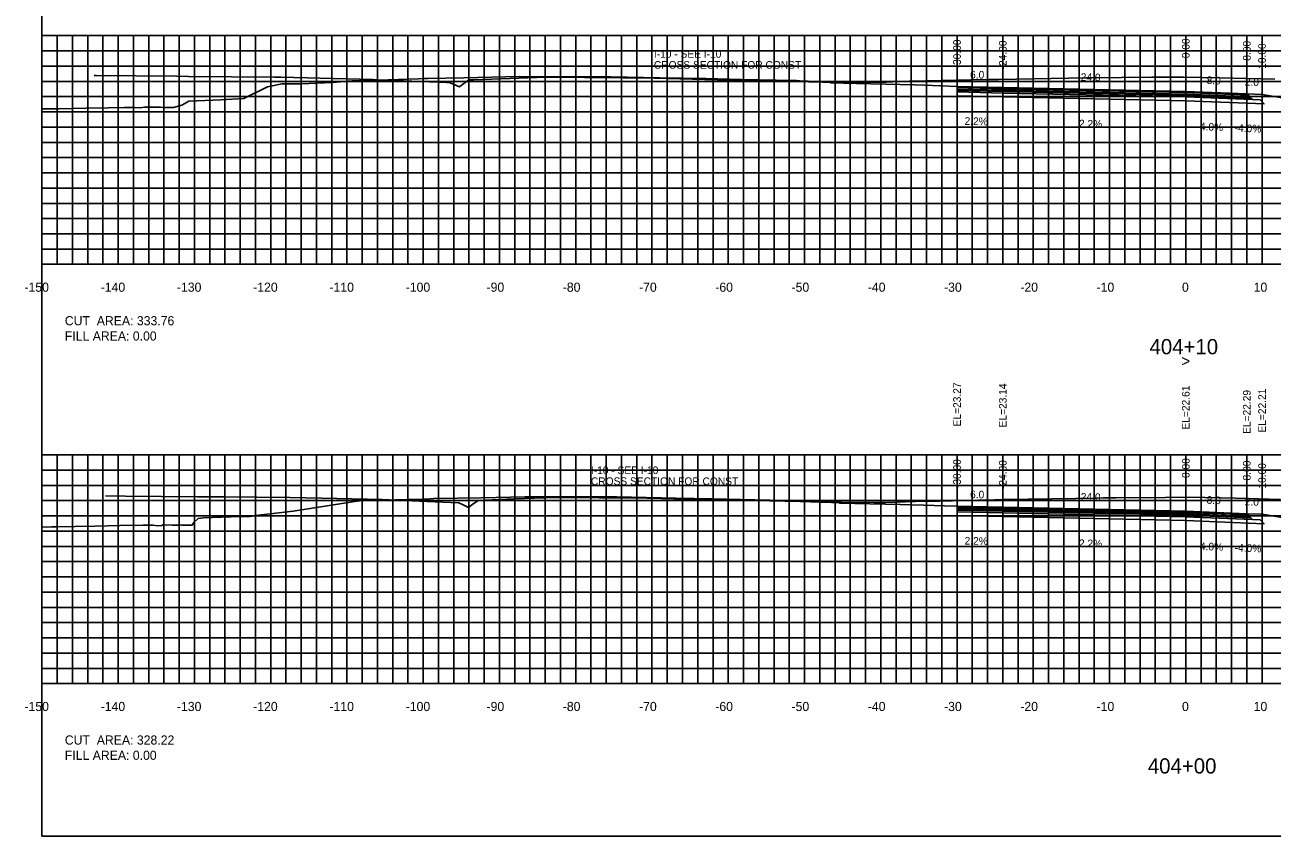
# Model space of a CAD drawing. Extents: x 1800976 to 1805104, y 250057 to 250580.
# Drawn here: x 1802478.8 to 1802642.3, y 250079.4 to 250185.8 of the extents above; entities that cross this region are included whole.
import ezdxf

# ---------------------------------------------------------------- set-up
doc = ezdxf.new("R2010")
doc.units = 0
for name, color, linetype in [('1', 7, 'Continuous'), ('10', 7, 'Continuous'), ('3', 7, 'Continuous'), ('4', 7, 'Continuous'), ('60', 7, 'Continuous'), ('ANNO-TXT', 7, 'Continuous'), ('BASE', 7, 'Continuous'), ('CL-CNST', 7, 'Continuous'), ('Level 62', 7, 'Continuous'), ('LOWER BINDER', 7, 'Continuous'), ('M-ROADS', 7, 'Continuous'), ('UPPER BINDER', 7, 'Continuous'), ('WEARING', 7, 'Continuous')]:
    doc.layers.add(name, color=color, linetype=linetype)

msp = doc.modelspace()

# ---------------------------------------------------------------- linework, layer by layer
for p, q in [((1802601, 250177.76), (1802601, 250179.76)), ((1802607, 250177.62), (1802607, 250179.62)), ((1802631, 250177.1), (1802631, 250179.1)), ((1802639, 250176.78), (1802639, 250178.78)), ((1802641, 250176.7), (1802641, 250178.7)), ((1802601, 250122.7), (1802601, 250124.7)), ((1802607, 250122.57), (1802607, 250124.57)), ((1802631, 250122.04), (1802631, 250124.04)), ((1802639, 250121.72), (1802639, 250123.72)), ((1802641, 250121.64), (1802641, 250123.64))]:
    msp.add_line(p, q)
msp.add_lwpolyline([(1802481, 250079.43), (1802781, 250079.43), (1802781, 250269.43), (1802481, 250269.43)], close=True)
at = {"layer": '60'}
for p, q in [((1802480.94, 250184.43), (1802481, 250184.43)), ((1802481, 250154.43), (1802481, 250184.43)), ((1802480.94, 250174.43), (1802481, 250174.43)), ((1802480.94, 250164.43), (1802481, 250164.43)), ((1802480.94, 250154.43), (1802481, 250154.43)), ((1802481, 250154.43), (1802781, 250154.43)), ((1802481, 250154.37), (1802481, 250154.43)), ((1802491, 250154.37), (1802491, 250154.43)), ((1802501, 250154.37), (1802501, 250154.43)), ((1802511, 250154.37), (1802511, 250154.43)), ((1802521, 250154.37), (1802521, 250154.43)), ((1802531, 250154.37), (1802531, 250154.43)), ((1802541, 250154.37), (1802541, 250154.43)), ((1802551, 250154.37), (1802551, 250154.43)), ((1802561, 250154.37), (1802561, 250154.43)), ((1802571, 250154.37), (1802571, 250154.43)), ((1802581, 250154.37), (1802581, 250154.43)), ((1802591, 250154.37), (1802591, 250154.43)), ((1802601, 250154.37), (1802601, 250154.43)), ((1802611, 250154.37), (1802611, 250154.43)), ((1802621, 250154.37), (1802621, 250154.43)), ((1802631, 250154.37), (1802631, 250154.43)), ((1802641, 250154.37), (1802641, 250154.43)), ((1802480.94, 250129.43), (1802481, 250129.43)), ((1802481, 250099.43), (1802481, 250129.43)), ((1802480.94, 250119.43), (1802481, 250119.43)), ((1802480.94, 250109.43), (1802481, 250109.43)), ((1802480.94, 250099.43), (1802481, 250099.43)), ((1802481, 250099.43), (1802781, 250099.43)), ((1802481, 250099.37), (1802481, 250099.43)), ((1802491, 250099.37), (1802491, 250099.43)), ((1802501, 250099.37), (1802501, 250099.43)), ((1802511, 250099.37), (1802511, 250099.43)), ((1802521, 250099.37), (1802521, 250099.43)), ((1802531, 250099.37), (1802531, 250099.43)), ((1802541, 250099.37), (1802541, 250099.43)), ((1802551, 250099.37), (1802551, 250099.43)), ((1802561, 250099.37), (1802561, 250099.43)), ((1802571, 250099.37), (1802571, 250099.43)), ((1802581, 250099.37), (1802581, 250099.43)), ((1802591, 250099.37), (1802591, 250099.43)), ((1802601, 250099.37), (1802601, 250099.43)), ((1802611, 250099.37), (1802611, 250099.43)), ((1802621, 250099.37), (1802621, 250099.43)), ((1802631, 250099.37), (1802631, 250099.43)), ((1802641, 250099.37), (1802641, 250099.43))]:
    msp.add_line(p, q, dxfattribs=at)
at = {"layer": 'BASE'}
for points in [[(1802601, 250177.04), (1802607, 250176.9), (1802631, 250176.38), (1802639.75, 250176.03), (1802640.75, 250175.99), (1802641.27, 250175.47), (1802631, 250175.88), (1802607, 250176.4), (1802601, 250176.54)], [(1802601, 250121.98), (1802607, 250121.85), (1802631, 250121.32), (1802639.75, 250120.97), (1802640.75, 250120.93), (1802641.27, 250120.41), (1802631, 250120.82), (1802607, 250121.35), (1802601, 250121.48)]]:
    msp.add_lwpolyline(points, close=True, dxfattribs=at)
at = {"layer": 'CL-CNST'}
for points in [[(1802487.83, 250179.19), (1802488.12, 250179.22), (1802498.64, 250179.11), (1802500.22, 250179.08), (1802511.5, 250178.97), (1802512.31, 250178.96), (1802524.36, 250178.67), (1802524.4, 250178.67), (1802524.43, 250178.67), (1802525, 250178.65), (1802534.03, 250178.28), (1802534.48, 250178.26), (1802534.54, 250178.23), (1802535.74, 250177.7), (1802535.8, 250177.74), (1802537, 250178.61), (1802537.62, 250178.64), (1802547.07, 250179), (1802557.24, 250178.89), (1802559.17, 250178.89), (1802561.33, 250178.84), (1802571.26, 250178.6), (1802574.19, 250178.53), (1802583.35, 250178.32), (1802583.64, 250178.31), (1802584.36, 250178.28), (1802584.39, 250178.24), (1802584.41, 250178.23), (1802587.83, 250178.15), (1802595.44, 250177.97), (1802596.72, 250177.92), (1802601, 250177.74)], [(1802601, 250177.76), (1802607, 250177.62), (1802631, 250177.1), (1802639, 250176.78), (1802641, 250176.7), (1802671, 250171.7), (1802675, 250171.7), (1802694.66, 250176.61)], [(1802489.32, 250124.04), (1802491.97, 250124.03), (1802501.41, 250123.94), (1802504.83, 250123.92), (1802513.51, 250123.84), (1802517.69, 250123.74), (1802525.6, 250123.56), (1802531.5, 250123.31), (1802535.67, 250123.14), (1802536.23, 250122.86), (1802536.93, 250122.55), (1802537.49, 250122.96), (1802538.19, 250123.47), (1802542.94, 250123.65), (1802548.27, 250123.85), (1802554.01, 250123.79), (1802560.36, 250123.77), (1802567.52, 250123.6), (1802572.45, 250123.48), (1802580.38, 250123.3), (1802584.55, 250123.2), (1802585.23, 250123.17), (1802585.55, 250123.16), (1802585.57, 250123.14), (1802585.61, 250123.11), (1802593.56, 250122.92), (1802596.64, 250122.85), (1802599.34, 250122.76), (1802601, 250122.69)], [(1802601, 250122.7), (1802607, 250122.57), (1802631, 250122.04), (1802639, 250121.72), (1802641, 250121.64), (1802671, 250116.64), (1802675, 250116.64), (1802694.63, 250121.55)]]:
    msp.add_lwpolyline(points, dxfattribs=at)
at = {"layer": 'Level 62'}
for p, q in [((1802481, 250184.43), (1802781, 250184.43)), ((1802481, 250154.43), (1802481, 250184.43)), ((1802483, 250154.43), (1802483, 250184.43)), ((1802485, 250154.43), (1802485, 250184.43)), ((1802487, 250154.43), (1802487, 250184.43)), ((1802489, 250154.43), (1802489, 250184.43)), ((1802491, 250154.43), (1802491, 250184.43)), ((1802493, 250154.43), (1802493, 250184.43)), ((1802495, 250154.43), (1802495, 250184.43)), ((1802497, 250154.43), (1802497, 250184.43)), ((1802499, 250154.43), (1802499, 250184.43)), ((1802501, 250154.43), (1802501, 250184.43)), ((1802503, 250154.43), (1802503, 250184.43)), ((1802505, 250154.43), (1802505, 250184.43)), ((1802507, 250154.43), (1802507, 250184.43)), ((1802509, 250154.43), (1802509, 250184.43)), ((1802511, 250154.43), (1802511, 250184.43)), ((1802513, 250154.43), (1802513, 250184.43)), ((1802515, 250154.43), (1802515, 250184.43)), ((1802517, 250154.43), (1802517, 250184.43)), ((1802519, 250154.43), (1802519, 250184.43)), ((1802521, 250154.43), (1802521, 250184.43)), ((1802523, 250154.43), (1802523, 250184.43)), ((1802525, 250154.43), (1802525, 250184.43)), ((1802527, 250154.43), (1802527, 250184.43)), ((1802529, 250154.43), (1802529, 250184.43)), ((1802531, 250154.43), (1802531, 250184.43)), ((1802533, 250154.43), (1802533, 250184.43)), ((1802535, 250154.43), (1802535, 250184.43)), ((1802537, 250154.43), (1802537, 250184.43)), ((1802539, 250154.43), (1802539, 250184.43)), ((1802541, 250154.43), (1802541, 250184.43)), ((1802543, 250154.43), (1802543, 250184.43)), ((1802545, 250154.43), (1802545, 250184.43)), ((1802547, 250154.43), (1802547, 250184.43)), ((1802549, 250154.43), (1802549, 250184.43)), ((1802551, 250154.43), (1802551, 250184.43)), ((1802553, 250154.43), (1802553, 250184.43)), ((1802555, 250154.43), (1802555, 250184.43)), ((1802557, 250154.43), (1802557, 250184.43)), ((1802559, 250154.43), (1802559, 250184.43)), ((1802561, 250154.43), (1802561, 250184.43)), ((1802563, 250154.43), (1802563, 250184.43)), ((1802565, 250154.43), (1802565, 250184.43)), ((1802567, 250154.43), (1802567, 250184.43)), ((1802569, 250154.43), (1802569, 250184.43)), ((1802571, 250154.43), (1802571, 250184.43)), ((1802573, 250154.43), (1802573, 250184.43)), ((1802575, 250154.43), (1802575, 250184.43)), ((1802577, 250154.43), (1802577, 250184.43)), ((1802579, 250154.43), (1802579, 250184.43)), ((1802581, 250154.43), (1802581, 250184.43)), ((1802583, 250154.43), (1802583, 250184.43)), ((1802585, 250154.43), (1802585, 250184.43)), ((1802587, 250154.43), (1802587, 250184.43)), ((1802589, 250154.43), (1802589, 250184.43)), ((1802591, 250154.43), (1802591, 250184.43)), ((1802593, 250154.43), (1802593, 250184.43)), ((1802595, 250154.43), (1802595, 250184.43)), ((1802597, 250154.43), (1802597, 250184.43)), ((1802599, 250154.43), (1802599, 250184.43)), ((1802601, 250154.43), (1802601, 250184.43)), ((1802603, 250154.43), (1802603, 250184.43)), ((1802605, 250154.43), (1802605, 250184.43)), ((1802607, 250154.43), (1802607, 250184.43)), ((1802609, 250154.43), (1802609, 250184.43)), ((1802611, 250154.43), (1802611, 250184.43)), ((1802613, 250154.43), (1802613, 250184.43)), ((1802615, 250154.43), (1802615, 250184.43)), ((1802617, 250154.43), (1802617, 250184.43)), ((1802619, 250154.43), (1802619, 250184.43)), ((1802621, 250154.43), (1802621, 250184.43)), ((1802623, 250154.43), (1802623, 250184.43)), ((1802625, 250154.43), (1802625, 250184.43)), ((1802627, 250154.43), (1802627, 250184.43)), ((1802629, 250154.43), (1802629, 250184.43)), ((1802631, 250154.43), (1802631, 250184.43)), ((1802633, 250154.43), (1802633, 250184.43)), ((1802635, 250154.43), (1802635, 250184.43)), ((1802637, 250154.43), (1802637, 250184.43)), ((1802639, 250154.43), (1802639, 250184.43)), ((1802641, 250154.43), (1802641, 250184.43)), ((1802481, 250182.43), (1802781, 250182.43)), ((1802481, 250180.43), (1802781, 250180.43)), ((1802481, 250178.43), (1802781, 250178.43)), ((1802481, 250176.43), (1802929.9, 250176.43)), ((1802481, 250174.43), (1802781, 250174.43)), ((1802481, 250172.43), (1802781, 250172.43)), ((1802481, 250170.43), (1802781, 250170.43)), ((1802481, 250168.43), (1802781, 250168.43)), ((1802481, 250166.43), (1802781, 250166.43)), ((1802481, 250164.43), (1802781, 250164.43)), ((1802481, 250162.43), (1802781, 250162.43)), ((1802481, 250160.43), (1802781, 250160.43)), ((1802481, 250158.43), (1802781, 250158.43)), ((1802481, 250156.43), (1802781, 250156.43)), ((1802481, 250154.43), (1802781, 250154.43)), ((1802481, 250129.43), (1802781, 250129.43)), ((1802481, 250099.43), (1802481, 250129.43)), ((1802483, 250099.43), (1802483, 250129.43)), ((1802485, 250099.43), (1802485, 250129.43)), ((1802487, 250099.43), (1802487, 250129.43)), ((1802489, 250099.43), (1802489, 250129.43)), ((1802491, 250099.43), (1802491, 250129.43)), ((1802493, 250099.43), (1802493, 250129.43)), ((1802495, 250099.43), (1802495, 250129.43)), ((1802497, 250099.43), (1802497, 250129.43)), ((1802499, 250099.43), (1802499, 250129.43)), ((1802501, 250099.43), (1802501, 250129.43)), ((1802503, 250099.43), (1802503, 250129.43)), ((1802505, 250099.43), (1802505, 250129.43)), ((1802507, 250099.43), (1802507, 250129.43)), ((1802509, 250099.43), (1802509, 250129.43)), ((1802511, 250099.43), (1802511, 250129.43)), ((1802513, 250099.43), (1802513, 250129.43)), ((1802515, 250099.43), (1802515, 250129.43)), ((1802517, 250099.43), (1802517, 250129.43)), ((1802519, 250099.43), (1802519, 250129.43)), ((1802521, 250099.43), (1802521, 250129.43)), ((1802523, 250099.43), (1802523, 250129.43)), ((1802525, 250099.43), (1802525, 250129.43)), ((1802527, 250099.43), (1802527, 250129.43)), ((1802529, 250099.43), (1802529, 250129.43)), ((1802531, 250099.43), (1802531, 250129.43)), ((1802533, 250099.43), (1802533, 250129.43)), ((1802535, 250099.43), (1802535, 250129.43)), ((1802537, 250099.43), (1802537, 250129.43)), ((1802539, 250099.43), (1802539, 250129.43)), ((1802541, 250099.43), (1802541, 250129.43)), ((1802543, 250099.43), (1802543, 250129.43)), ((1802545, 250099.43), (1802545, 250129.43)), ((1802547, 250099.43), (1802547, 250129.43)), ((1802549, 250099.43), (1802549, 250129.43)), ((1802551, 250099.43), (1802551, 250129.43)), ((1802553, 250099.43), (1802553, 250129.43)), ((1802555, 250099.43), (1802555, 250129.43)), ((1802557, 250099.43), (1802557, 250129.43)), ((1802559, 250099.43), (1802559, 250129.43)), ((1802561, 250099.43), (1802561, 250129.43)), ((1802563, 250099.43), (1802563, 250129.43)), ((1802565, 250099.43), (1802565, 250129.43)), ((1802567, 250099.43), (1802567, 250129.43)), ((1802569, 250099.43), (1802569, 250129.43)), ((1802571, 250099.43), (1802571, 250129.43)), ((1802573, 250099.43), (1802573, 250129.43)), ((1802575, 250099.43), (1802575, 250129.43)), ((1802577, 250099.43), (1802577, 250129.43)), ((1802579, 250099.43), (1802579, 250129.43)), ((1802581, 250099.43), (1802581, 250129.43)), ((1802583, 250099.43), (1802583, 250129.43)), ((1802585, 250099.43), (1802585, 250129.43)), ((1802587, 250099.43), (1802587, 250129.43)), ((1802589, 250099.43), (1802589, 250129.43)), ((1802591, 250099.43), (1802591, 250129.43)), ((1802593, 250099.43), (1802593, 250129.43)), ((1802595, 250099.43), (1802595, 250129.43)), ((1802597, 250099.43), (1802597, 250129.43)), ((1802599, 250099.43), (1802599, 250129.43)), ((1802601, 250099.43), (1802601, 250129.43)), ((1802603, 250099.43), (1802603, 250129.43)), ((1802605, 250099.43), (1802605, 250129.43)), ((1802607, 250099.43), (1802607, 250129.43)), ((1802609, 250099.43), (1802609, 250129.43)), ((1802611, 250099.43), (1802611, 250129.43)), ((1802613, 250099.43), (1802613, 250129.43)), ((1802615, 250099.43), (1802615, 250129.43)), ((1802617, 250099.43), (1802617, 250129.43)), ((1802619, 250099.43), (1802619, 250129.43)), ((1802621, 250099.43), (1802621, 250129.43)), ((1802623, 250099.43), (1802623, 250129.43)), ((1802625, 250099.43), (1802625, 250129.43)), ((1802627, 250099.43), (1802627, 250129.43)), ((1802629, 250099.43), (1802629, 250129.43)), ((1802631, 250099.43), (1802631, 250129.43)), ((1802633, 250099.43), (1802633, 250129.43)), ((1802635, 250099.43), (1802635, 250129.43)), ((1802637, 250099.43), (1802637, 250129.43)), ((1802639, 250099.43), (1802639, 250129.43)), ((1802641, 250099.43), (1802641, 250129.43)), ((1802481, 250127.43), (1802781, 250127.43)), ((1802481, 250125.43), (1802781, 250125.43)), ((1802481, 250123.43), (1802781, 250123.43)), ((1802481, 250121.43), (1802781, 250121.43)), ((1802481, 250119.43), (1802781, 250119.43)), ((1802481, 250117.43), (1802781, 250117.43)), ((1802481, 250115.43), (1802781, 250115.43)), ((1802481, 250113.43), (1802781, 250113.43)), ((1802481, 250111.43), (1802781, 250111.43)), ((1802481, 250109.43), (1802781, 250109.43)), ((1802481, 250107.43), (1802781, 250107.43)), ((1802481, 250105.43), (1802781, 250105.43)), ((1802481, 250103.43), (1802781, 250103.43)), ((1802481, 250101.43), (1802781, 250101.43)), ((1802481, 250099.43), (1802781, 250099.43))]:
    msp.add_line(p, q, dxfattribs=at)
at = {"layer": 'LOWER BINDER'}
for points in [[(1802607, 250177.28), (1802631, 250176.76), (1802639.36, 250176.42), (1802639.55, 250176.22), (1802631, 250176.57), (1802607, 250177.09), (1802601, 250177.23), (1802601, 250177.42)], [(1802607, 250177.09), (1802631, 250176.57), (1802639.55, 250176.22), (1802639.75, 250176.03), (1802631, 250176.38), (1802607, 250176.9), (1802601, 250177.04), (1802601, 250177.23)], [(1802607, 250122.23), (1802631, 250121.7), (1802639.36, 250121.37), (1802639.55, 250121.17), (1802631, 250121.51), (1802607, 250122.04), (1802601, 250122.17), (1802601, 250122.36)], [(1802607, 250122.04), (1802631, 250121.51), (1802639.55, 250121.17), (1802639.75, 250120.97), (1802631, 250121.32), (1802607, 250121.85), (1802601, 250121.98), (1802601, 250122.17)]]:
    msp.add_lwpolyline(points, close=True, dxfattribs=at)
at = {"layer": 'M-ROADS'}
for points in [[(1802481, 250174.81), (1802483.21, 250174.84), (1802486.82, 250174.91), (1802489.74, 250174.95), (1802491.83, 250175), (1802492.57, 250174.99), (1802493.12, 250174.99), (1802493.87, 250174.96), (1802494.45, 250175.05), (1802494.58, 250175.06), (1802494.87, 250175.06), (1802495.73, 250175.03), (1802496.52, 250175.03), (1802496.99, 250175.02), (1802497.06, 250175.02), (1802497.53, 250175.02), (1802498.27, 250175.01), (1802499.33, 250175.32), (1802500.26, 250175.81), (1802504.45, 250176.02), (1802507.49, 250176.2), (1802510.56, 250177.71), (1802511.25, 250177.85), (1802512.46, 250178.09), (1802514.02, 250178.09), (1802515, 250178.09), (1802519.11, 250178.3), (1802521.67, 250178.5), (1802523.74, 250178.56), (1802530.39, 250178.77), (1802531.04, 250178.79), (1802531.63, 250178.81), (1802536.33, 250178.9), (1802543.61, 250179.05), (1802548.43, 250179.04), (1802555.61, 250179.02), (1802562.03, 250178.9), (1802568.06, 250178.79), (1802572.7, 250178.68), (1802579.59, 250178.54), (1802579.94, 250178.53), (1802580.84, 250178.47), (1802581.5, 250178.44), (1802583.87, 250178.34), (1802586.9, 250178.32), (1802590.95, 250178.29), (1802593.39, 250178.39), (1802594.73, 250178.44), (1802597.03, 250178.49), (1802602.81, 250178.61), (1802605.17, 250178.66), (1802605.97, 250178.66), (1802606.42, 250178.66), (1802617.99, 250178.88), (1802618.59, 250178.89), (1802626.53, 250178.96), (1802630.69, 250178.99), (1802635.41, 250178.88), (1802642.66, 250178.72)], [(1802481, 250120.01), (1802481.59, 250119.97), (1802482.25, 250119.98), (1802482.87, 250119.99), (1802485.35, 250120.05), (1802487.92, 250120.1), (1802491.2, 250120.16), (1802494.26, 250120.21), (1802494.77, 250120.21), (1802495.55, 250120.21), (1802496.21, 250120.13), (1802496.74, 250120.15), (1802496.87, 250120.24), (1802498.07, 250120.22), (1802498.13, 250120.22), (1802499, 250120.21), (1802499.21, 250120.24), (1802499.38, 250120.2), (1802499.42, 250120.23), (1802500.37, 250120.23), (1802500.71, 250120.23), (1802500.92, 250120.56), (1802501.48, 250121.08), (1802502.17, 250121.16), (1802503.32, 250121.21), (1802507.03, 250121.36), (1802508.32, 250121.37), (1802509.05, 250121.48), (1802513.96, 250122.07), (1802516.17, 250122.42), (1802522.31, 250123.37), (1802522.39, 250123.38), (1802522.43, 250123.39), (1802522.67, 250123.4), (1802528.92, 250123.58), (1802531.16, 250123.64), (1802531.93, 250123.67), (1802532.4, 250123.69), (1802538.63, 250123.82), (1802544.38, 250123.94), (1802551.3, 250123.92), (1802556.38, 250123.91), (1802564.14, 250123.76), (1802568.83, 250123.67), (1802574.48, 250123.53), (1802580.36, 250123.4), (1802580.83, 250123.38), (1802581.61, 250123.34), (1802582.54, 250123.31), (1802584.64, 250123.21), (1802585.87, 250123.21), (1802590.15, 250123.19), (1802591.72, 250123.19), (1802593, 250123.23), (1802595.49, 250123.3), (1802598.68, 250123.37), (1802603.8, 250123.49), (1802605.93, 250123.53), (1802606.78, 250123.55), (1802607.18, 250123.56), (1802616.6, 250123.73), (1802619.37, 250123.77), (1802620.17, 250123.78), (1802621.84, 250123.8), (1802628.36, 250123.86), (1802631.45, 250123.88), (1802637.58, 250123.74), (1802643.43, 250123.6)]]:
    msp.add_lwpolyline(points, dxfattribs=at)
at = {"layer": 'UPPER BINDER'}
for points in [[(1802639.36, 250176.42), (1802639.16, 250176.62), (1802631, 250176.95), (1802607, 250177.47), (1802601, 250177.61), (1802601, 250177.42), (1802607, 250177.28), (1802631, 250176.76)], [(1802639.36, 250121.37), (1802639.16, 250121.56), (1802631, 250121.89), (1802607, 250122.42), (1802601, 250122.55), (1802601, 250122.36), (1802607, 250122.23), (1802631, 250121.7)]]:
    msp.add_lwpolyline(points, close=True, dxfattribs=at)
at = {"layer": 'WEARING'}
for points in [[(1802639.16, 250176.62), (1802639, 250176.78), (1802631, 250177.1), (1802607, 250177.62), (1802601, 250177.76), (1802601, 250177.61), (1802607, 250177.47), (1802631, 250176.95)], [(1802639.16, 250121.56), (1802639, 250121.72), (1802631, 250122.04), (1802607, 250122.57), (1802601, 250122.7), (1802601, 250122.55), (1802607, 250122.42), (1802631, 250121.89)]]:
    msp.add_lwpolyline(points, close=True, dxfattribs=at)

# ---------------------------------------------------------------- texts
at = {"layer": '1'}
for s, p in [('404+10', (1802626.24, 250142.63)), ('404+00', (1802626.02, 250087.63))]:
    msp.add_text(s, height=2, dxfattribs=at).set_placement(p)
at = {"layer": '10'}
for s, p in [('-150', (1802478.7, 250150.83)), ('-140', (1802488.7, 250150.83)), ('-130', (1802498.7, 250150.83)), ('-120', (1802508.7, 250150.83)), ('-110', (1802518.7, 250150.83)), ('-100', (1802528.7, 250150.83)), ('-90', (1802539.3, 250150.83)), ('-80', (1802549.3, 250150.83)), ('-70', (1802559.3, 250150.83)), ('-60', (1802569.3, 250150.83)), ('-50', (1802579.3, 250150.83)), ('-40', (1802589.3, 250150.83)), ('-30', (1802599.3, 250150.83)), ('-20', (1802609.3, 250150.83)), ('-10', (1802619.3, 250150.83)), ('0', (1802630.5, 250150.83)), ('10', (1802639.9, 250150.83)), ('-150', (1802478.7, 250095.83)), ('-140', (1802488.7, 250095.83)), ('-130', (1802498.7, 250095.83)), ('-120', (1802508.7, 250095.83)), ('-110', (1802518.7, 250095.83)), ('-100', (1802528.7, 250095.83)), ('-90', (1802539.3, 250095.83)), ('-80', (1802549.3, 250095.83)), ('-70', (1802559.3, 250095.83)), ('-60', (1802569.3, 250095.83)), ('-50', (1802579.3, 250095.83)), ('-40', (1802589.3, 250095.83)), ('-30', (1802599.3, 250095.83)), ('-20', (1802609.3, 250095.83)), ('-10', (1802619.3, 250095.83)), ('0', (1802630.5, 250095.83)), ('10', (1802639.9, 250095.83))]:
    msp.add_text(s, height=1.2, dxfattribs=at).set_placement(p)
at = {"layer": '3'}
for s, p in [('I-10 - SEE I-10 ', (1802561.25, 250181.53)), ('CROSS SECTION FOR CONST ', (1802561.25, 250180.09)), ('I-10 - SEE I-10 ', (1802552.99, 250126.92)), ('CROSS SECTION FOR CONST ', (1802552.99, 250125.48))]:
    msp.add_text(s, height=1, dxfattribs=at).set_placement(p)
for s, p in [('-30.00', (1802601.5, 250180.13)), ('-24.00', (1802607.5, 250180)), ('0.00', (1802631.5, 250181.46)), ('8.00', (1802639.5, 250181.14)), ('10.00', (1802641.5, 250180.07)), ('EL=23.27', (1802601.5, 250133.17)), ('EL=23.14', (1802607.5, 250133.04)), ('EL=22.61', (1802631.5, 250132.76)), ('EL=22.29', (1802639.5, 250132.19)), ('EL=22.21', (1802641.5, 250132.36)), ('-30.00', (1802601.5, 250125.08)), ('-24.00', (1802607.5, 250124.95)), ('0.00', (1802631.5, 250126.4)), ('8.00', (1802639.5, 250126.08)), ('10.00', (1802641.5, 250125.01))]:
    msp.add_text(s, height=1, rotation=90, dxfattribs=at).set_placement(p)
at = {"layer": '4'}
for s, rotation, p in [('6.0', 358.7397, (1802602.7, 250178.82)), ('24.0', 358.7397, (1802617.21, 250178.5)), ('8.0', 357.7094, (1802633.72, 250178.09)), ('2.0', 357.7094, (1802638.72, 250177.89)), ('2.2%', 358.7397, (1802601.98, 250172.73)), ('2.2%', 358.7397, (1802616.98, 250172.4)), ('-4.0%', 357.7094, (1802632.39, 250172.04)), ('-4.0%', 357.7094, (1802637.39, 250171.84)), ('6.0', 358.7397, (1802602.7, 250123.76)), ('24.0', 358.7397, (1802617.21, 250123.44)), ('8.0', 357.7094, (1802633.72, 250123.03)), ('2.0', 357.7094, (1802638.72, 250122.83)), ('2.2%', 358.7397, (1802601.98, 250117.68)), ('2.2%', 358.7397, (1802616.98, 250117.35)), ('-4.0%', 357.7094, (1802632.39, 250116.98)), ('-4.0%', 357.7094, (1802637.39, 250116.78))]:
    msp.add_text(s, height=1, rotation=rotation, dxfattribs=at).set_placement(p)
at = {"layer": '60'}
for s, height, p in [('-', 0.0001, (1802481, 250154.43)), ('>', 1.5, (1802630.39, 250141.01)), ('-', 0.0001, (1802481, 250099.43))]:
    msp.add_text(s, height=height, dxfattribs=at).set_placement(p)
at = {"layer": 'ANNO-TXT'}
for s, p in [('CUT  AREA: 333.76', (1802484, 250146.43)), ('FILL AREA: 0.00', (1802484, 250144.43)), ('CUT  AREA: 328.22', (1802484, 250091.43)), ('FILL AREA: 0.00', (1802484, 250089.43))]:
    msp.add_text(s, height=1.2, dxfattribs=at).set_placement(p)

doc.saveas('drawing.dxf')
